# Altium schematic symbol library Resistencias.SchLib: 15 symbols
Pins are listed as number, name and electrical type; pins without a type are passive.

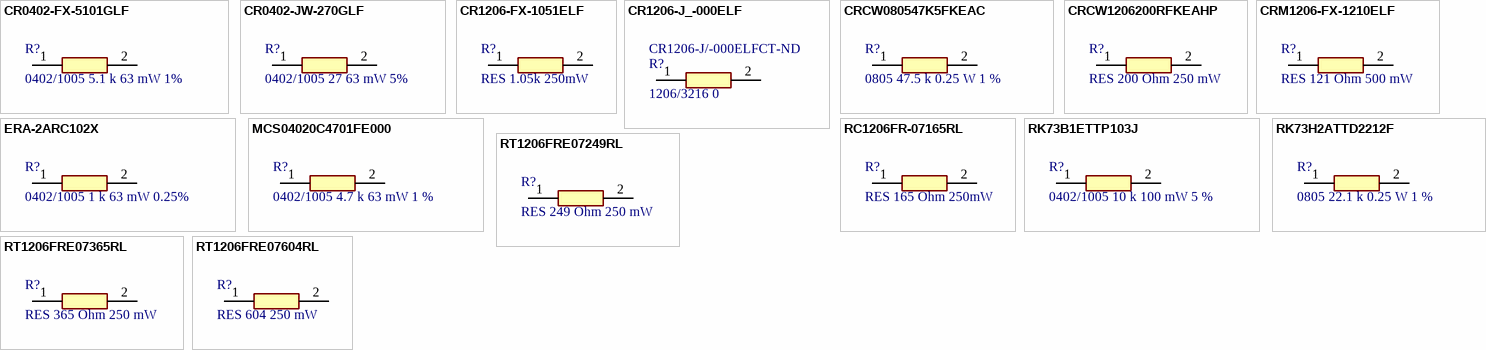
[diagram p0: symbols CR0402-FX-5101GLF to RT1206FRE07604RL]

## CR0402-FX-5101GLF
designator R?, comment 0402/1005 5.1 k 63 mW 1%
0402/1005 K 5.1 k 63 mW 1%; Manufacturer_Name: Bourns; Manufacturer_Part_Number: CR0402-FX-5101GLF; Voltage Rating (DC): 50V
footprint RESC1005X40N
pins: 1, 2

## CR0402-JW-270GLF
designator R?, comment 0402/1005 27 63 mW 5%
Manufacturer_Name: Bourns; Manufacturer_Part_Number: CR0402-JW-270GLF
footprint RESC1005X40N
pins: 1, 2

## CR1206-FX-1051ELF
designator R?, comment RES 1.05k 250mW
1206 k 1.05 250 mW 1%; Manufacturer_Name: Bourns; Manufacturer_Part_Number: CR1206-FX-1051ELF
footprint RESC3216X75N
pins: 1, 2

## CR1206-J_-000ELF
designator R?, comment 1206/3216 0  Supplier Part Number 1: CR1206-J/-000ELFCT-ND
Manufacturer_Name: Bourns; Manufacturer_Part_Number: CR1206-J/-000ELF
footprint RESC3216X75N
pins: 1, 2

## CRCW080547K5FKEAC
designator R?, comment 0805 47.5 k 0.25 W 1 %
Manufacturer_Name: Vishay; Manufacturer_Part_Number: CRCW080547K5FKEAC
footprint RESC2012X60N
pins: 1, 2

## CRCW1206200RFKEAHP
designator R?, comment RES 200 Ohm 250 mW
1206 200 250 mW 1%; Manufacturer_Name: Vishay; Manufacturer_Part_Number: CRCW1206200RFKEAHP
footprint RESC3216X75N
pins: 1, 2

## CRM1206-FX-1210ELF
designator R?, comment RES 121 Ohm 500 mW
1206 121 500 mW 1%; Manufacturer_Name: Vishay; Manufacturer_Part_Number: WSL1206R0200FEB
footprint RESC3216X75N
pins: 1, 2

## ERA-2ARC102X
designator R?, comment 0402/1005 1 k 63 mW 0.25%
0402/1005 k 1 63 mW 0.25%; Manufacturer_Name: Panasonic; Manufacturer_Part_Number: ERA-2ARC102X; Value: 1kR; Max Power Dissipation: 63mW; Temperature Coefficient: 10ppm/°C
footprint ERA2AED122X
pins: 1, 2

## MCS04020C4701FE000
designator R?, comment 0402/1005 4.7 k 63 mW 1 %
0402/1005 k 4.7 63 mW 1 %; Manufacturer_Name: Vishay; Manufacturer_Part_Number: MCS04020C4701FE000; Manufacturer: Vishay Beyschlag; Value: 4.7kR; Power Rating: 100mW; Tolerance: 1%; Voltage Rating: 50V; Temperature Coefficient: 50ppm/°C
footprint RESC1005X37N
pins: 1, 2

## RC1206FR-07165RL
designator R?, comment RES 165 Ohm 250mW
1206 165 250 mW 1%; Manufacturer_Name: Panasonic; Manufacturer_Part_Number: ERJ-8ENF1400V
footprint RESC3216X75N
pins: 1, 2

## RK73B1ETTP103J
designator R?, comment 0402/1005 10 k 100 mW 5 %
0402/1005 k 10 100 mW 5 %; Manufacturer_Name: KOA Speer; Manufacturer_Part_Number: RK73B1ETTP103J
footprint RESC1005X40N
pins: 1, 2

## RK73H2ATTD2212F
designator R?, comment 0805 22.1 k 0.25 W 1 %
Manufacturer_Name: KOA Speer; Manufacturer_Part_Number: RK73H2ATTD2212F
footprint RESC2012X60N
pins: 1, 2

## RT1206FRE07249RL
designator R?, comment RES 249 Ohm 250 mW
1206 249 250 mW 1%; Manufacturer_Name: Panasonic; Manufacturer_Part_Number: ERJ-8ENF1400V
footprint RESC2012X60N
pins: 1, 2

## RT1206FRE07365RL
designator R?, comment RES 365 Ohm 250 mW
1206 365 250 mW 1%; Manufacturer_Name: Panasonic; Manufacturer_Part_Number: ERJ-8ENF1400V
footprint RESC1005X40N
pins: 1, 2

## RT1206FRE07604RL
designator R?, comment RES 604 250 mW
1206 604 250 mW 1%; Manufacturer_Name: YAGEO; Manufacturer_Part_Number: RT1206FRE131KL
footprint RESC3116X65N
pins: 1, 2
